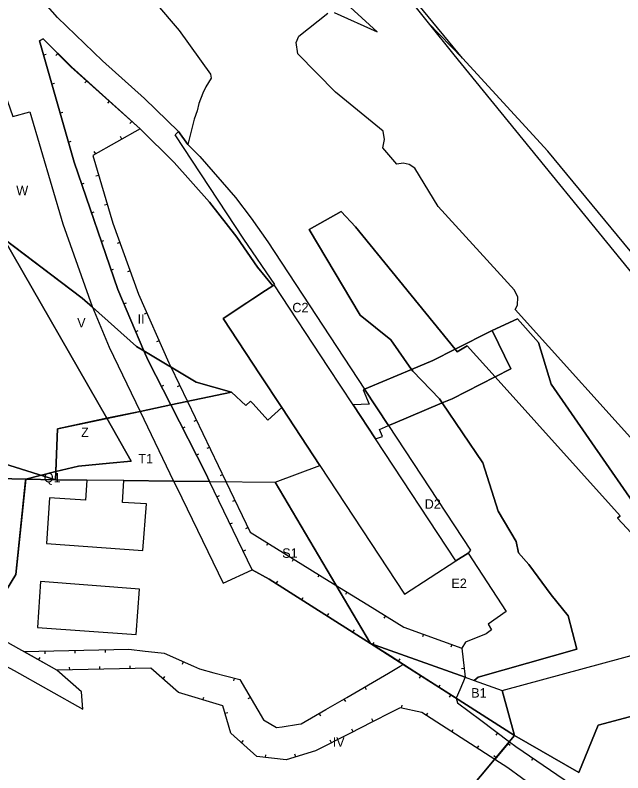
# Model space of a CAD drawing. Extents: x -749314 to -746497, y -1026537 to -1024935.
# Drawn here: x -747327.2 to -747166.5, y -1025726.2 to -1025525.6 of the extents above; entities that cross this region are included whole.
import ezdxf

# ---------------------------------------------------------------- set-up
doc = ezdxf.new("R2010")
doc.units = 0
for name, color, linetype in [('Default', 7, 'Continuous'), ('K_CD1', 7, 'Continuous'), ('K_DOSZDC1', 7, 'Continuous'), ('K_NH_SZDC', 7, 'Continuous'), ('K_SZDC1', 7, 'Continuous'), ('K_VBP', 7, 'Continuous')]:
    doc.layers.add(name, color=color, linetype=linetype)

msp = doc.modelspace()

# ---------------------------------------------------------------- linework, layer by layer
for points in [[(-747319.74, -1025536.09), (-747319.02, -1025535.89)], [(-747315.96, -1025535.69), (-747316.49, -1025536.22)], [(-747308.26, -1025542.98), (-747308.76, -1025543.53)], [(-747317.55, -1025543.78), (-747316.83, -1025543.58)], [(-747302.32, -1025548.34), (-747302.82, -1025548.89)], [(-747315.35, -1025551.48), (-747314.63, -1025551.27)], [(-747296.38, -1025553.7), (-747296.89, -1025554.26)], [(-747313.16, -1025559.17), (-747312.44, -1025558.97)], [(-747298.97, -1025558.4), (-747299.34, -1025557.74)], [(-747305.93, -1025562.33), (-747306.3, -1025561.68)], [(-747305.13, -1025568.04), (-747305.85, -1025568.25)], [(-747309.64, -1025570.33), (-747308.93, -1025570.09)], [(-747302.84, -1025575.7), (-747303.56, -1025575.92)], [(-747307.06, -1025577.9), (-747306.35, -1025577.66)], [(-747304.47, -1025585.47), (-747303.76, -1025585.23)], [(-747299.51, -1025585.79), (-747300.22, -1025586.04)], [(-747301.89, -1025593.05), (-747301.18, -1025592.8)], [(-747296.8, -1025593.31), (-747297.51, -1025593.57)], [(-747298.49, -1025602.03), (-747297.8, -1025601.74)], [(-747292.39, -1025604.45), (-747293.07, -1025604.75)], [(-747295.34, -1025609.38), (-747294.65, -1025609.09)], [(-747289.15, -1025611.77), (-747289.84, -1025612.07)], [(-747288.57, -1025623.87), (-747287.91, -1025623.53)], [(-747283.67, -1025623.67), (-747284.34, -1025623.99)], [(-747279.28, -1025632.8), (-747279.96, -1025633.12)], [(-747282.95, -1025634.92), (-747282.28, -1025634.58)], [(-747275.82, -1025640.01), (-747276.49, -1025640.34)], [(-747279.32, -1025642.05), (-747278.65, -1025641.71)], [(-747272.36, -1025647.22), (-747273.03, -1025647.55)], [(-747273.85, -1025653.08), (-747273.18, -1025652.75)], [(-747269.09, -1025654.03), (-747269.77, -1025654.35)], [(-747270.37, -1025660.28), (-747269.7, -1025659.96)], [(-747265.63, -1025661.24), (-747266.31, -1025661.57)], [(-747260.39, -1025665.33), (-747260.78, -1025665.96)], [(-747266.89, -1025667.49), (-747266.22, -1025667.16)], [(-747253.59, -1025669.54), (-747253.98, -1025670.18)], [(-747258.16, -1025676.09), (-747257.76, -1025675.45)], [(-747246.79, -1025673.76), (-747247.18, -1025674.39)], [(-747239.47, -1025678.28), (-747239.87, -1025678.92)], [(-747251.41, -1025680.38), (-747251.01, -1025679.74)], [(-747244.66, -1025684.66), (-747244.25, -1025684.03)], [(-747229.3, -1025684.59), (-747229.69, -1025685.23)], [(-747237.9, -1025688.95), (-747237.5, -1025688.32)], [(-747219.24, -1025689.47), (-747219.5, -1025690.18)], [(-747232.67, -1025692.28), (-747232.26, -1025691.65)], [(-747303.43, -1025693.59), (-747303.41, -1025694.34)], [(-747211.72, -1025692.18), (-747211.97, -1025692.89)], [(-747321.01, -1025696.29), (-747320.64, -1025695.64)], [(-747319.42, -1025693.96), (-747319.4, -1025694.71)], [(-747311.42, -1025693.77), (-747311.41, -1025694.52)], [(-747282.75, -1025696.78), (-747283.06, -1025697.46)], [(-747225.83, -1025696.65), (-747225.42, -1025696.02)], [(-747312.8, -1025698.91), (-747312.82, -1025698.16)], [(-747304.81, -1025698.74), (-747304.82, -1025697.99)], [(-747296.81, -1025698.56), (-747296.83, -1025697.81)], [(-747208.43, -1025698.59), (-747209.17, -1025698.68)], [(-747288.11, -1025701.27), (-747287.61, -1025700.71)], [(-747269.31, -1025701.09), (-747269.5, -1025701.81)], [(-747219.92, -1025700.44), (-747220.32, -1025701.07)], [(-747234.76, -1025703.42), (-747234.38, -1025704.07)], [(-747215.17, -1025703.48), (-747214.77, -1025702.84)], [(-747212.02, -1025705.49), (-747212.42, -1025706.13)], [(-747277.54, -1025706.86), (-747277.33, -1025706.14)], [(-747264.99, -1025706.24), (-747265.64, -1025706.61)], [(-747240.26, -1025706.63), (-747239.88, -1025707.28)], [(-747225, -1025709.02), (-747224.84, -1025708.29)], [(-747271.73, -1025710.37), (-747271.01, -1025710.17)], [(-747246.8, -1025710.44), (-747246.42, -1025711.09)], [(-747218.47, -1025710.99), (-747218.06, -1025710.36)], [(-747232.53, -1025712.58), (-747232.88, -1025711.91)], [(-747237.82, -1025715.28), (-747238.16, -1025714.61)], [(-747211.74, -1025715.31), (-747211.33, -1025714.68)], [(-747199.65, -1025715.56), (-747200.1, -1025716.16)], [(-747267.36, -1025718.21), (-747266.86, -1025717.65)], [(-747243.59, -1025718.22), (-747243.93, -1025717.55)], [(-747205.01, -1025719.64), (-747204.6, -1025719.01)], [(-747196.85, -1025718.39), (-747196.27, -1025718.87)], [(-747261.04, -1025722.13), (-747260.95, -1025721.38)], [(-747253.02, -1025721.96), (-747253.24, -1025721.24)], [(-747200, -1025722.16), (-747200.58, -1025721.68)], [(-747190.25, -1025722.29), (-747190.68, -1025722.91)]]:
    msp.add_lwpolyline(points)
at = {"layer": 'Default'}
msp.add_lwpolyline([(-747327.84, -1025552.37), (-747323.35, -1025551.14), (-747314.62, -1025580.82), (-747306.89, -1025602.7), (-747306.8, -1025602.91), (-747295.12, -1025613.27), (-747293.17, -1025614.44), (-747300.11, -1025598.25), (-747311.65, -1025564.46), (-747320.79, -1025532.42), (-747319.86, -1025531.81), (-747312.53, -1025539.26), (-747294.18, -1025555.69), (-747285.17, -1025564.57), (-747275.8, -1025575.12), (-747268.56, -1025584.4), (-747263.14, -1025592.27), (-747259.04, -1025597.24), (-747258.7, -1025597.02), (-747258.54, -1025596.91), (-747266.77, -1025584.9), (-747284.9, -1025557.24), (-747284.04, -1025556.36), (-747293.03, -1025547.63), (-747304.14, -1025537.68), (-747316, -1025526.23), (-747327.12, -1025513.48)], dxfattribs=at)
for points in [[(-747357.69, -1025555.06), (-747337.88, -1025528.12), (-747334.95, -1025536.15), (-747329.97, -1025546.35), (-747327.84, -1025552.37), (-747323.35, -1025551.14), (-747314.62, -1025580.82), (-747306.89, -1025602.7), (-747306.8, -1025602.91), (-747309.47, -1025600.54), (-747330.28, -1025584.74), (-747335.45, -1025575.7), (-747336.38, -1025574.1)], [(-747330.25, -1025584.76), (-747309.47, -1025600.54), (-747306.8, -1025602.91), (-747302.37, -1025613.46), (-747294.18, -1025630.48), (-747302.96, -1025632.32)], [(-747292.06, -1025617.02), (-747293.17, -1025614.44), (-747295.12, -1025613.27), (-747306.8, -1025602.91), (-747302.37, -1025613.46), (-747294.18, -1025630.48), (-747286.08, -1025628.77)], [(-747237.83, -1025628.76), (-747231.94, -1025637.71), (-747230.08, -1025637.17), (-747230.88, -1025635.25), (-747228.45, -1025634.23), (-747234.79, -1025624.58), (-747235.2, -1025624.75), (-747233.61, -1025628.61)], [(-747285.3, -1025648.94), (-747275.81, -1025649.03), (-747276.82, -1025646.95), (-747286.08, -1025628.77), (-747294.18, -1025630.48)], [(-747275.81, -1025649.03), (-747285.3, -1025648.94), (-747284.48, -1025650.65), (-747272.22, -1025675.93), (-747264.5, -1025672.44)]]:
    msp.add_lwpolyline(points, close=True, dxfattribs=at)
at = {"layer": 'K_CD1'}
for points in [[(-747208.9, -1025537.01), (-747220.47, -1025522.93), (-747241.05, -1025497.59), (-747278.95, -1025450.46), (-747279.42, -1025450.84), (-747217.97, -1025527.65)], [(-747284.04, -1025556.36), (-747293.03, -1025547.63), (-747304.14, -1025537.68), (-747316, -1025526.23), (-747327.12, -1025513.48), (-747316.37, -1025498.86), (-747311.37, -1025502.69), (-747303.85, -1025508.85), (-747290.08, -1025522.29), (-747283.88, -1025529.61), (-747275.54, -1025541.17), (-747275.35, -1025542.26), (-747276.77, -1025544.52), (-747277.61, -1025546.19), (-747278.64, -1025548.98), (-747279.07, -1025550.95), (-747279.9, -1025553.1), (-747281.55, -1025559.79)], [(-747145.79, -1025606.78), (-747161.2, -1025592.04), (-747186.31, -1025561.6), (-747208.9, -1025537.01), (-747217.97, -1025527.65), (-747211.2, -1025536.12), (-747152.53, -1025608.14), (-747152.08, -1025609.14)], [(-747293.17, -1025614.44), (-747279.34, -1025622.73), (-747270.02, -1025625.4), (-747266.23, -1025628.9), (-747264.96, -1025627.77), (-747264.3, -1025628.5), (-747260.41, -1025632.81), (-747256.72, -1025629.47), (-747262.43, -1025620.77), (-747272.23, -1025605.86), (-747265.92, -1025601.73), (-747264.33, -1025600.7), (-747260.98, -1025598.51), (-747259.04, -1025597.24), (-747263.14, -1025592.27), (-747268.56, -1025584.4), (-747275.8, -1025575.12), (-747285.17, -1025564.57), (-747294.18, -1025555.69), (-747312.53, -1025539.26), (-747319.86, -1025531.81), (-747320.79, -1025532.42), (-747311.65, -1025564.46), (-747300.11, -1025598.25)], [(-747383.69, -1025664.23), (-747392, -1025656.27), (-747397.7, -1025649.74), (-747415.7, -1025624.23), (-747451.38, -1025570.91), (-747454.06, -1025565.5), (-747455.21, -1025560.92), (-747462.97, -1025562), (-747439.26, -1025600.34), (-747417.19, -1025631.71), (-747414.46, -1025635.53), (-747399.81, -1025654.4), (-747390.04, -1025667.02), (-747357.84, -1025683.59), (-747342.1, -1025691.24), (-747327.46, -1025699.06), (-747309.33, -1025709.32), (-747309.7, -1025704.76), (-747316.22, -1025698.99), (-747329.04, -1025691.76), (-747335.84, -1025688.09), (-747370.63, -1025669.34)], [(-747216.76, -1025617.03), (-747210.84, -1025614.05), (-747237.16, -1025581.59), (-747240.96, -1025577.56), (-747249.48, -1025582.3), (-747235.97, -1025605), (-747227.81, -1025611.53), (-747222.38, -1025619.38)], [(-747224.28, -1025678.85), (-747210.67, -1025670.06), (-747231.94, -1025637.71), (-747237.83, -1025628.76), (-747244.32, -1025618.89), (-747258.7, -1025597.02), (-747259.04, -1025597.24), (-747260.98, -1025598.51), (-747264.33, -1025600.7), (-747265.92, -1025601.73), (-747272.23, -1025605.86), (-747262.43, -1025620.77), (-747256.72, -1025629.47), (-747246.65, -1025644.8)], [(-747200.27, -1025621.3), (-747167.16, -1025658.09), (-747167.86, -1025658.73), (-747156.98, -1025670.46), (-747156.24, -1025669.78), (-747152.14, -1025674.15), (-747150.94, -1025673.04), (-747185.44, -1025623.24), (-747188.83, -1025612.23), (-747194.35, -1025605.97), (-747201.01, -1025609.1), (-747196.13, -1025619.18)], [(-747210.3, -1025614.72), (-747207.63, -1025613.13), (-747200.27, -1025621.3), (-747196.13, -1025619.18), (-747201.01, -1025609.1), (-747210.84, -1025614.05)], [(-747214.25, -1025628.23), (-747211.67, -1025627.14), (-747200.27, -1025621.3), (-747207.63, -1025613.13), (-747210.3, -1025614.72), (-747210.84, -1025614.05), (-747216.76, -1025617.03), (-747222.38, -1025619.38), (-747222.05, -1025619.86), (-747214.96, -1025627.18)], [(-747286.08, -1025628.77), (-747270.02, -1025625.4), (-747279.34, -1025622.73), (-747293.17, -1025614.44), (-747292.06, -1025617.02)], [(-747222.05, -1025619.86), (-747222.38, -1025619.38), (-747233.74, -1025624.14), (-747234.79, -1025624.58), (-747228.45, -1025634.23), (-747227.33, -1025633.75), (-747214.25, -1025628.23), (-747214.96, -1025627.18)], [(-747180.93, -1025684.57), (-747178.68, -1025693.46), (-747204.73, -1025700.85), (-747205.8, -1025701.71), (-747198.39, -1025704.35), (-747140.17, -1025688.58), (-747150.94, -1025673.04), (-747152.14, -1025674.15), (-747156.24, -1025669.78), (-747156.98, -1025670.46), (-747167.86, -1025658.73), (-747167.16, -1025658.09), (-747200.27, -1025621.3), (-747211.67, -1025627.14), (-747214.25, -1025628.23), (-747203.49, -1025644.13), (-747199.44, -1025656.88), (-747194.73, -1025664.89), (-747194.07, -1025667.93), (-747191.35, -1025671.03), (-747185.48, -1025679.09)], [(-747246.65, -1025644.8), (-747256.72, -1025629.47), (-747260.41, -1025632.81), (-747264.3, -1025628.5), (-747264.96, -1025627.77), (-747266.23, -1025628.9), (-747270.02, -1025625.4), (-747286.08, -1025628.77), (-747276.82, -1025646.95), (-747275.81, -1025649.03), (-747258.47, -1025649.19)], [(-747202.6, -1025689.37), (-747208.06, -1025691.54), (-747209.08, -1025693.13), (-747208.16, -1025700.86), (-747205.8, -1025701.71), (-747204.73, -1025700.85), (-747178.68, -1025693.46), (-747180.93, -1025684.57), (-747185.48, -1025679.09), (-747191.35, -1025671.03), (-747194.07, -1025667.93), (-747194.73, -1025664.89), (-747199.44, -1025656.88), (-747203.49, -1025644.13), (-747214.25, -1025628.23), (-747227.33, -1025633.75), (-747228.45, -1025634.23), (-747206.78, -1025667.24), (-747207.41, -1025668), (-747197.31, -1025683.43), (-747202.13, -1025686.79), (-747201.21, -1025688.3)], [(-747316.56, -1025648.56), (-747316.06, -1025635.07), (-747294.18, -1025630.48), (-747302.96, -1025632.32), (-747296.55, -1025643.69), (-747302.27, -1025644.22), (-747310.5, -1025644.98), (-747316.48, -1025646.44)], [(-747207.41, -1025668), (-747197.31, -1025683.43), (-747202.13, -1025686.79), (-747201.21, -1025688.3), (-747202.6, -1025689.37), (-747208.06, -1025691.54), (-747209.08, -1025693.13), (-747208.16, -1025700.86), (-747233.26, -1025691.9), (-747258.47, -1025649.19), (-747246.65, -1025644.8), (-747224.28, -1025678.85), (-747210.67, -1025670.06)], [(-747349.43, -1025647.85), (-747342.85, -1025647.99), (-747324.44, -1025648.39), (-747324.49, -1025648.86), (-747327.06, -1025673.68), (-747335.84, -1025688.09), (-747370.63, -1025669.34), (-747377.22, -1025658.62), (-747367.72, -1025659.21), (-747367.27, -1025659.23), (-747367.45, -1025662.07), (-747363.7, -1025662.32), (-747363.72, -1025662.57), (-747361.25, -1025662.73), (-747361.39, -1025664.78), (-747357.81, -1025665.02), (-747357.67, -1025662.96), (-747350.59, -1025663.43), (-747350.24, -1025657.43), (-747350.04, -1025657.44), (-747349.68, -1025651.14)], [(-747327.06, -1025673.68), (-747324.49, -1025648.86), (-747324.44, -1025648.43)], [(-747264.5, -1025672.44), (-747275.81, -1025649.03), (-747258.47, -1025649.19), (-747233.26, -1025691.9), (-747260.06, -1025674.87)], [(-747233.26, -1025691.9), (-747208.16, -1025700.86), (-747205.8, -1025701.71), (-747198.39, -1025704.35), (-747195.11, -1025716.31)]]:
    msp.add_lwpolyline(points, close=True, dxfattribs=at)
for points in [[(-747242.88, -1025524.86), (-747231.5, -1025529.99), (-747254.86, -1025508.52)], [(-747290.08, -1025522.29), (-747283.88, -1025529.61), (-747275.54, -1025541.17), (-747275.35, -1025542.26), (-747276.77, -1025544.52), (-747277.61, -1025546.19), (-747278.64, -1025548.98), (-747279.07, -1025550.95), (-747279.9, -1025553.1), (-747281.55, -1025559.79), (-747278.39, -1025563.03), (-747268.93, -1025573.88), (-747264.77, -1025579.32), (-747260.41, -1025585.55), (-747234.79, -1025624.58), (-747233.74, -1025624.14), (-747222.38, -1025619.38), (-747227.81, -1025611.53), (-747235.97, -1025605), (-747249.48, -1025582.3), (-747240.96, -1025577.56), (-747237.16, -1025581.59), (-747210.84, -1025614.05), (-747201.01, -1025609.1), (-747194.35, -1025605.97), (-747188.83, -1025612.23), (-747185.44, -1025623.24), (-747150.94, -1025673.04)], [(-747158.88, -1025643.56), (-747194.93, -1025603.51), (-747194.39, -1025602.39), (-747194.28, -1025600.21), (-747195.18, -1025598.43), (-747215.29, -1025576.25), (-747221.53, -1025566.08), (-747222.99, -1025565.09), (-747224.55, -1025564.73), (-747226.23, -1025565.05), (-747229.94, -1025560.68), (-747229.57, -1025558.46), (-747229.9, -1025556.28), (-747242.45, -1025546.01), (-747252.44, -1025535.78), (-747252.91, -1025532.79), (-747252.17, -1025531.13), (-747244.52, -1025525.04)], [(-747338.64, -1025578.39), (-747309.47, -1025600.54), (-747330.25, -1025584.76), (-747302.96, -1025632.32), (-747316.06, -1025635.07), (-747316.48, -1025646.44), (-747324.44, -1025648.39), (-747316.56, -1025648.56), (-747346.98, -1025639.05)], [(-747346.98, -1025639.05), (-747316.56, -1025648.56), (-747324.44, -1025648.39), (-747342.85, -1025647.99)], [(-747135.65, -1025703.61), (-747172.98, -1025713.55), (-747178.16, -1025726.07), (-747195.11, -1025716.31), (-747198.39, -1025704.35), (-747140.17, -1025688.58)]]:
    msp.add_lwpolyline(points, dxfattribs=at)
at = {"layer": 'K_DOSZDC1'}
for points in [[(-747284.9, -1025557.24), (-747284.04, -1025556.36), (-747281.55, -1025559.79), (-747278.39, -1025563.03), (-747268.93, -1025573.88), (-747264.77, -1025579.32), (-747260.41, -1025585.55), (-747234.79, -1025624.58), (-747235.2, -1025624.75), (-747233.61, -1025628.61), (-747237.83, -1025628.76), (-747244.32, -1025618.89), (-747258.7, -1025597.02), (-747258.54, -1025596.91), (-747266.77, -1025584.9)], [(-747316.56, -1025648.56), (-747316.48, -1025646.44), (-747310.5, -1025644.98), (-747302.27, -1025644.22), (-747296.55, -1025643.69), (-747302.96, -1025632.32), (-747294.18, -1025630.48), (-747285.3, -1025648.94), (-747298.49, -1025648.82), (-747308.26, -1025648.73)], [(-747231.94, -1025637.71), (-747230.08, -1025637.17), (-747230.88, -1025635.25), (-747228.45, -1025634.23), (-747206.78, -1025667.24), (-747207.41, -1025668), (-747210.67, -1025670.06)], [(-747324.44, -1025648.39), (-747316.48, -1025646.44), (-747316.56, -1025648.56)], [(-747321.28, -1025687.69), (-747295.22, -1025689.56), (-747294.36, -1025677.54), (-747320.49, -1025675.56)]]:
    msp.add_lwpolyline(points, close=True, dxfattribs=at)
for points in [[(-747335.84, -1025688.09), (-747327.06, -1025673.68), (-747324.44, -1025648.39), (-747316.56, -1025648.56), (-747308.26, -1025648.73), (-747308.66, -1025653.95), (-747318.11, -1025653.35), (-747318.93, -1025665.42), (-747293.46, -1025667.29), (-747292.48, -1025655), (-747298.87, -1025654.59), (-747298.49, -1025648.82), (-747285.3, -1025648.94), (-747284.48, -1025650.65), (-747272.22, -1025675.93), (-747264.5, -1025672.44), (-747260.06, -1025674.87), (-747233.26, -1025691.9), (-747195.11, -1025716.31), (-747245.05, -1025776.02)], [(-747327.46, -1025699.06), (-747309.33, -1025709.32), (-747309.7, -1025704.76), (-747316.22, -1025698.99), (-747329.04, -1025691.76)], [(-747149.75, -1025824.07), (-747180.36, -1025811.49), (-747220.97, -1025790.36), (-747222.79, -1025794.6), (-747247.64, -1025780.1), (-747245.05, -1025776.02), (-747195.11, -1025716.31), (-747178.16, -1025726.07), (-747172.98, -1025713.55), (-747135.65, -1025703.61)]]:
    msp.add_lwpolyline(points, dxfattribs=at)
at = {"layer": 'K_NH_SZDC'}
for points in [[(-747284.04, -1025556.36), (-747281.55, -1025559.79)], [(-747330.25, -1025584.76), (-747302.96, -1025632.32), (-747296.55, -1025643.69), (-747302.27, -1025644.22), (-747310.5, -1025644.98), (-747316.48, -1025646.44), (-747324.44, -1025648.39)], [(-747210.67, -1025670.06), (-747207.41, -1025668)], [(-747264.5, -1025672.44), (-747260.06, -1025674.87), (-747233.26, -1025691.9)], [(-747233.26, -1025691.9), (-747217.81, -1025701.79), (-747212.07, -1025705.46), (-747204.08, -1025710.57), (-747195.11, -1025716.31)], [(-747195.11, -1025716.31), (-747178.16, -1025726.07), (-747172.98, -1025713.55), (-747135.65, -1025703.61), (-747112.73, -1025755.01), (-747112.65, -1025765.98), (-747112.56, -1025778.81), (-747107.45, -1025791.93), (-747093.88, -1025807.61), (-747082.15, -1025821.16), (-747066.55, -1025843.35), (-747060.4, -1025848.43), (-747036.46, -1025868.24), (-747022.18, -1025849.67), (-747007.3, -1025830.45)]]:
    msp.add_lwpolyline(points, dxfattribs=at)
at = {"layer": 'K_SZDC1'}
for points in [[(-747308.26, -1025648.73), (-747308.66, -1025653.95), (-747318.11, -1025653.35), (-747318.93, -1025665.42), (-747293.46, -1025667.29), (-747292.48, -1025655), (-747298.87, -1025654.59), (-747298.49, -1025648.82)], [(-747295.22, -1025689.56), (-747294.36, -1025677.54), (-747320.49, -1025675.56), (-747321.28, -1025687.69)]]:
    msp.add_lwpolyline(points, close=True, dxfattribs=at)
at = {"layer": 'K_VBP'}
for points in [[(-747320.79, -1025532.42), (-747319.86, -1025531.81), (-747312.34, -1025539.29), (-747294.18, -1025555.69), (-747306.71, -1025562.77), (-747301.37, -1025580.61), (-747294.61, -1025599.42), (-747286.56, -1025617.64), (-747286.05, -1025618.71), (-747281.66, -1025627.84), (-747271.47, -1025649.07), (-747265.06, -1025662.43), (-747244.15, -1025675.39), (-747233.97, -1025681.69), (-747224.42, -1025687.61), (-747209.08, -1025693.13), (-747208.16, -1025700.86), (-747209.57, -1025704.16), (-747210.54, -1025706.44), (-747221.2, -1025699.62), (-747228.03, -1025695.24), (-747233.26, -1025691.9), (-747260.02, -1025674.91), (-747264.5, -1025672.44), (-747275.81, -1025649.03), (-747276.82, -1025646.95), (-747286.08, -1025628.77), (-747292.06, -1025617.02), (-747293.17, -1025614.44), (-747300.11, -1025598.25), (-747311.65, -1025564.46)], [(-747324.92, -1025694.09), (-747297.12, -1025693.44), (-747292.83, -1025693.94), (-747288.6, -1025694.43), (-747287.77, -1025694.53), (-747280.09, -1025697.97), (-747278.5, -1025698.68), (-747274.63, -1025699.69), (-747267.77, -1025701.49), (-747261.55, -1025712.11), (-747258.13, -1025714.19), (-747256.62, -1025713.97), (-747252.29, -1025713.32), (-747251.55, -1025713.21), (-747245.01, -1025709.4), (-747239.51, -1025706.19), (-747228.5, -1025699.78), (-747225.35, -1025697.95), (-747224.55, -1025697.48), (-747216.65, -1025702.53), (-747210.54, -1025706.44), (-747210.18, -1025707.66), (-747207.13, -1025709.95), (-747204.05, -1025712.26), (-747196.47, -1025717.94), (-747200.38, -1025722.61), (-747219.64, -1025710.24), (-747225.38, -1025708.93), (-747227.64, -1025710.07), (-747232.92, -1025712.78), (-747238.69, -1025715.72), (-747247.76, -1025720.34), (-747255.57, -1025722.74), (-747263.26, -1025721.88), (-747270.21, -1025715.66), (-747272.28, -1025708.45), (-747283.99, -1025704.91), (-747291.31, -1025698.44), (-747316.22, -1025698.99)]]:
    msp.add_lwpolyline(points, close=True, dxfattribs=at)
msp.add_lwpolyline([(-747166.02, -1025760.02), (-747171.54, -1025752.01), (-747178.68, -1025741.14), (-747182.4, -1025735.47), (-747185.02, -1025733.55), (-747189.68, -1025730.14), (-747196.87, -1025724.87), (-747200.38, -1025722.61), (-747196.47, -1025717.94), (-747194.8, -1025719.19), (-747178.37, -1025730.38), (-747176.08, -1025733.78), (-747161.96, -1025754.73)], dxfattribs=at)

# ---------------------------------------------------------------- texts
for s, p in [('W', (-747326.93, -1025573.25)), ('C2', (-747253.9, -1025604.25)), ('II', (-747294.83, -1025607.25)), ('V', (-747310.82, -1025608.25)), ('Z', (-747309.78, -1025637.25)), ('T1', (-747294.64, -1025644.25)), ('Q1', (-747319.65, -1025649.25)), ('D2', (-747218.9, -1025656.25)), ('S1', (-747256.59, -1025669.25)), ('E2', (-747211.84, -1025677.25)), ('B1', (-747206.6, -1025706.25)), ('IV', (-747243.23, -1025719.25))]:
    msp.add_text(s, height=2.5).set_placement(p)

doc.saveas('drawing.dxf')
